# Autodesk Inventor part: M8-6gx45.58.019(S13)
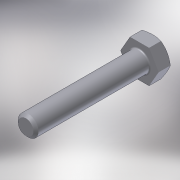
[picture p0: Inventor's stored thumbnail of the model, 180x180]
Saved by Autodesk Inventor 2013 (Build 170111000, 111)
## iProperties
Shininess: 20.0
Length Units: 11269
Angle Units: 11279
Time Units: 11290
Mass Units: 11283
Length Display Precision: 3
Angle Display Precision: 2
Created: 2001-07
Part Number: M8-6gx45.58.019(S13)
Document SubType Name: Modeling
Designer: TEvgeniy
Material: Steel, Mild
Description: Болт M8-6gx45.58.019(S12) ГОСТ 7798-70
Density: 7.86 g/cm^3
Density: 7.86
Volumn: 3.0242481679368165
Area: 16.322259291362354
PropertySet Name: Model Information
Control State: 0
Master: False
Checked Out: False
Checked Out Date: 2008-10-15
Last Check In Date: 2008-10-15
Author: TEvgeniy
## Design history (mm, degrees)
sketch "Sketch1"
  geometry: L1 (482.08, 469.325)-(474.575, 469.325); L2 (485.833, 462.825)-(482.08, 469.325); L3 (482.08, 456.325)-(485.833, 462.825); L4 (474.575, 456.325)-(482.08, 456.325); L5 (470.822, 462.825)-(474.575, 456.325); L6 (474.575, 469.325)-(470.822, 462.825); C1 r 6.5 at (478.327, 462.825)
  constraints: 12 end point, 6 tangent, 3 parallel, 1 centre point, 1 horizontal, 1 other
  dimensions: "d1" = 120 deg angle of L1 L2; "d3" = 120 deg angle of L5 L6; "d5" = 13 diameter of C1
extrude "ExtrusionBlind1" new body sketch "Sketch1" distance "d6" = 5.3; taper "d7" = 0 deg
sketch "Sketch2"
  geometry: C1 r 6.4 at (478.327, -462.825)
  constraints: 1 centre point
  dimensions: "d12" = 12.8 diameter of C1
extrude "ExtrusionThru1" sketch "Sketch2" stored distance "d13" = 0.13; taper "d14" = 60 deg
sketch "Sketch3"
  geometry: L1 (470.822, 462.825)-(471.322, 463.691); L2 (474.575, 469.325)-(475.575, 469.325); L3 (482.08, 469.325)-(482.58, 468.459); C1 r 4 at (478.327, 462.825); C2 r 6.5 at (478.327, 462.825)
  constraints: 6 end point, 3 tangent, 2 centre point, 1 coincident
  dimensions: "d16" = 8 diameter of C1
extrude "ExtrusionBlind2" join sketch "Sketch3" distance "d17" = 45; taper "d18" = 0 deg
fillet "Fillet1" dims "d19" = 0.5
chamfer "Chamfer1" distance "d20" = 1; stored, may be unused: second distance "d21" = 1, angle "d22" = 45 deg
body "Solid1"
other parameters: "d0" = 120 deg (derived), "d2" = 120 deg (derived), "d4" = 13 (derived), "d8" = 0, "d9" = 0, "d10" = 0, "d11" = 12.8 (derived), "d15" = 8 (derived)
